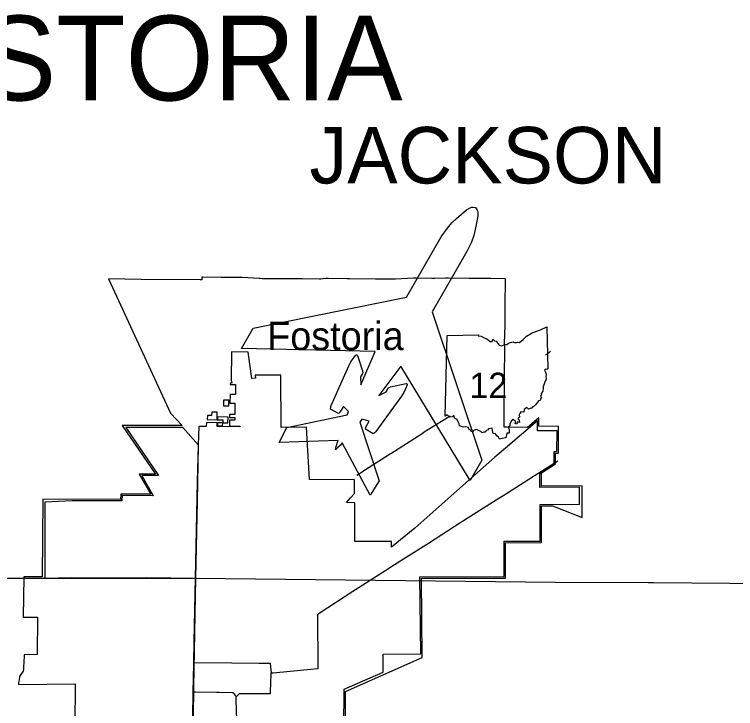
# Model space of a CAD drawing. Extents: x -232 to 448, y 619 to 1059.
# Drawn here: x 199.19 to 225.38, y 743.64 to 768.85 of the extents above; entities that cross this region are included whole.
import ezdxf

# ---------------------------------------------------------------- set-up
doc = ezdxf.new("R2010")
doc.units = 0
doc.layers.add('Default', color=7, linetype='Continuous')

msp = doc.modelspace()

# ---------------------------------------------------------------- linework, layer by layer
at = {"layer": 'Default'}
for p, q in [((202.606, 759.245), (204.864, 754.373)), ((205.999, 759.307), (205.997, 759.207)), ((214.831, 754.265), (214.913, 757.194)), ((214.831, 754.265), (214.913, 757.194)), ((207.071, 756.596), (207.064, 755.569)), ((207.681, 756.592), (207.071, 756.596)), ((207.82, 755.626), (207.681, 756.592)), ((208.868, 755.751), (207.93, 755.746)), ((207.93, 755.746), (207.944, 755.644)), ((208.879, 753.854), (208.868, 755.751)), ((207.035, 755.467), (207.034, 755.416)), ((207.086, 755.466), (207.035, 755.467)), ((207.064, 755.569), (207.086, 755.466)), ((207.944, 755.644), (207.82, 755.626)), ((207.034, 755.416), (207.224, 755.412)), ((207.224, 755.412), (207.216, 755.044)), ((207.026, 755.048), (207.02, 754.736)), ((207.216, 755.044), (207.026, 755.048)), ((206.975, 754.839), (206.785, 754.839)), ((206.785, 754.839), (206.785, 754.632)), ((206.975, 754.632), (206.975, 754.839)), ((207.02, 754.736), (207.192, 754.736)), ((207.192, 754.736), (207.192, 754.321)), ((206.357, 754.408), (206.355, 754.284)), ((206.557, 754.404), (206.357, 754.408)), ((206.556, 754.133), (206.557, 754.404)), ((206.785, 754.632), (206.975, 754.632)), ((206.2, 754.287), (206.198, 754.14)), ((206.355, 754.284), (206.2, 754.287)), ((206.571, 754.237), (206.569, 754.133)), ((206.95, 754.228), (206.571, 754.237)), ((206.946, 754.017), (206.95, 754.228)), ((207.192, 754.321), (207.006, 754.321)), ((207.006, 754.321), (207.006, 754.218)), ((207.006, 754.218), (207.192, 754.218)), ((207.192, 754.218), (207.192, 754.114)), ((218.235, 753.895), (218.238, 754.2)), ((206.164, 754.033), (206.161, 753.888)), ((206.555, 754.025), (206.164, 754.033)), ((206.198, 754.14), (206.556, 754.133)), ((206.555, 753.887), (206.555, 754.025)), ((206.566, 754.025), (206.564, 753.917)), ((206.564, 753.917), (206.754, 753.912)), ((206.756, 754.021), (206.566, 754.025)), ((206.569, 754.133), (206.758, 754.129)), ((206.754, 753.912), (206.756, 754.021)), ((206.758, 754.129), (206.756, 754.021)), ((206.756, 754.021), (206.946, 754.017)), ((207.192, 754.114), (207.006, 754.114)), ((207.006, 754.114), (207.006, 753.907)), ((207.006, 753.907), (207.384, 753.899)), ((207.384, 753.899), (207.384, 753.873)), ((218.182, 753.735), (218.186, 754.088)), ((218.953, 753.888), (218.235, 753.895)), ((209.799, 753.86), (208.879, 753.854)), ((209.905, 751.961), (209.799, 753.86)), ((218.901, 753.728), (218.182, 753.735)), ((218.894, 752.975), (218.901, 753.728)), ((218.787, 752.532), (218.791, 752.976)), ((218.791, 752.976), (218.894, 752.975)), ((218.276, 752.186), (218.787, 752.532)), ((204.312, 752.154), (203.727, 752.157)), ((203.727, 752.157), (204.149, 751.426)), ((204.43, 752.102), (203.816, 752.105)), ((203.816, 752.105), (204.238, 751.374)), ((218.278, 751.672), (218.276, 752.186)), ((211.537, 751.948), (209.905, 751.961)), ((211.543, 751.459), (211.537, 751.948)), ((219.712, 751.679), (218.278, 751.672)), ((219.709, 751.062), (219.712, 751.679)), ((203.061, 751.436), (203.048, 751.235)), ((203.109, 751.384), (203.096, 751.183)), ((200.231, 751.25), (200.199, 748.427)), ((203.048, 751.235), (200.231, 751.25)), ((201.305, 751.193), (201.289, 751.193)), ((203.096, 751.183), (201.305, 751.193)), ((218.279, 751.057), (219.709, 751.062)), ((218.282, 749.723), (218.279, 751.057)), ((218.731, 751.007), (219.809, 750.578)), ((212.886, 749.708), (211.552, 749.714)), ((212.885, 749.503), (212.886, 749.708)), ((216.976, 749.72), (218.282, 749.723)), ((216.979, 748.437), (216.976, 749.72)), ((199.532, 748.428), (199.515, 746.966)), ((200.199, 748.427), (199.532, 748.428)), ((213.918, 748.43), (216.979, 748.437)), ((213.946, 745.632), (213.918, 748.43)), ((213.97, 748.379), (217.03, 748.386)), ((213.999, 745.494), (213.97, 748.379)), ((199.515, 746.966), (200.028, 746.964)), ((200.028, 746.964), (200.026, 745.614)), ((199.545, 745.599), (199.537, 745.303)), ((200.026, 745.614), (199.545, 745.599)), ((201.401, 744.541), (201.381, 741.955))]:
    msp.add_line(p, q, dxfattribs=at)
for points in [[(212.292, 756.611), (207.442, 756.721), (207.865, 757.454), (213.433, 758.587), (214.695, 760.773), (214.914, 761.085), (215.077, 761.277), (215.245, 761.438), (215.613, 761.753), (215.741, 761.83), (215.794, 761.847), (215.842, 761.855), (215.934, 761.843)], [(215.934, 761.843), (215.989, 761.77), (216.006, 761.724), (216.019, 761.67), (216.016, 761.52), (215.927, 761.044), (215.872, 760.818), (215.787, 760.582), (215.626, 760.236), (214.364, 758.049), (216.167, 752.661), (215.744, 751.928), (213.223, 756.074)], [(205.997, 759.207), (205.943, 759.208), (203.796, 759.231), (202.606, 759.245)], [(207.408, 759.295), (206.734, 759.295), (206.697, 759.296), (206.04, 759.307), (205.999, 759.307)], [(210.324, 759.237), (210.271, 759.238), (209.647, 759.251), (209.595, 759.252), (209.544, 759.252), (209.076, 759.247), (208.985, 759.246), (208.971, 759.246), (208.19, 759.255), (208.116, 759.256), (208.084, 759.258), (207.46, 759.292), (207.408, 759.295)], [(212.975, 759.241), (212.919, 759.241), (212.422, 759.243), (212.332, 759.243), (212.311, 759.243), (211.372, 759.247), (211.311, 759.247), (211.261, 759.248), (210.598, 759.259), (210.496, 759.261), (210.387, 759.245), (210.324, 759.237)], [(214.899, 759.271), (214.844, 759.27), (214.459, 759.267), (214.362, 759.267), (214.348, 759.267), (213.799, 759.27), (213.732, 759.271), (213.691, 759.269), (213.032, 759.243), (212.975, 759.241)], [(217.021, 759.248), (216.488, 759.264), (216.412, 759.267), (216.384, 759.267), (215.801, 759.265), (215.727, 759.264), (215.694, 759.265), (214.951, 759.27), (214.899, 759.271)], [(217.011, 758.2), (217.011, 758.258), (217.021, 759.248)], [(216.992, 755.151), (216.987, 755.795), (216.986, 755.811), (216.988, 755.901), (217.001, 756.528), (217.001, 756.534), (216.999, 756.631), (216.995, 756.997), (216.994, 757.025), (216.996, 757.103), (217.008, 757.678), (217.009, 757.701), (217.009, 757.781), (217.011, 758.147), (217.011, 758.2)], [(214.913, 757.194), (216.05, 757.213), (216.032, 757.178), (216.139, 757.171), (216.253, 757.108), (216.349, 757.068), (216.467, 756.975), (216.538, 756.976), (216.568, 757.053), (216.622, 756.994), (216.686, 756.983), (216.796, 756.843), (216.888, 756.813), (216.997, 756.861), (217.079, 756.869), (217.139, 756.916), (217.295, 756.957), (217.339, 756.932), (217.421, 756.937), (217.463, 756.955), (217.535, 756.939), (217.662, 757.046), (217.792, 757.171), (217.993, 757.29), (218.292, 757.402), (218.53, 757.502), (218.564, 755.982)], [(214.913, 757.194), (216.05, 757.213), (216.032, 757.178), (216.139, 757.171), (216.253, 757.108), (216.349, 757.068), (216.467, 756.975), (216.538, 756.976), (216.568, 757.053), (216.622, 756.994), (216.686, 756.983), (216.796, 756.843), (216.888, 756.813), (216.997, 756.861), (217.079, 756.869), (217.139, 756.916), (217.295, 756.957), (217.339, 756.932), (217.421, 756.937), (217.463, 756.955), (217.535, 756.939), (217.662, 757.046), (217.792, 757.171), (217.993, 757.29), (218.292, 757.402), (218.53, 757.502), (218.564, 755.982)], [(210.854, 753.044), (210.875, 753.159), (210.909, 753.281), (210.946, 753.373), (208.802, 753.306), (209.087, 753.851), (211.275, 754.312), (211.329, 754.43), (211.138, 754.616), (211.039, 754.446), (211.002, 754.397), (210.98, 754.376), (210.957, 754.356), (210.672, 754.52), (210.675, 754.558), (210.68, 754.588), (210.687, 754.618), (210.697, 754.647), (211.339, 756.095), (211.414, 756.23), (211.5, 756.357), (211.596, 756.477), (211.612, 756.486), (211.627, 756.487), (211.64, 756.479), (211.649, 756.464), (211.833, 755.911), (211.838, 755.885), (211.842, 755.856), (211.842, 755.84), (211.834, 755.817), (211.76, 755.69), (211.776, 755.395), (212.292, 756.611)], [(218.473, 756.493), (218.552, 756.543), (218.618, 756.586), (218.665, 756.621)], [(213.223, 756.074), (212.428, 755.018), (212.691, 755.152), (212.764, 755.279), (212.781, 755.298), (212.795, 755.306), (212.822, 755.317), (212.846, 755.326), (213.418, 755.443), (213.435, 755.443), (213.448, 755.435), (213.455, 755.422), (213.455, 755.404), (213.4, 755.26), (213.333, 755.122), (213.253, 754.99), (212.32, 753.71), (212.3, 753.687), (212.278, 753.666), (212.254, 753.646), (212.222, 753.625), (211.938, 753.789), (211.943, 753.82), (211.951, 753.849), (211.975, 753.906), (212.073, 754.076), (211.815, 754.149), (211.741, 754.043), (212.436, 751.917), (212.106, 751.398), (211.092, 753.289), (211.031, 753.211), (210.942, 753.121), (210.854, 753.044)], [(218.564, 755.982), (218.529, 755.961), (218.474, 755.971), (218.438, 755.929), (218.483, 755.857), (218.504, 755.782), (218.485, 755.699), (218.504, 755.631), (218.491, 755.574), (218.457, 755.517), (218.445, 755.463), (218.416, 755.406), (218.419, 755.374), (218.391, 755.348), (218.396, 755.253), (218.382, 755.201), (218.387, 755.155), (218.342, 755.143), (218.352, 755.106), (218.323, 755.077), (218.33, 755.027), (218.297, 754.995), (218.329, 754.931), (218.303, 754.911), (218.282, 754.833), (218.225, 754.818), (218.109, 754.676), (218.068, 754.622), (218.022, 754.609), (217.997, 754.554), (217.941, 754.554), (217.855, 754.515), (217.8, 754.581), (217.704, 754.502), (217.692, 754.411), (217.57, 754.414), (217.575, 754.367), (217.548, 754.354), (217.523, 754.308), (217.537, 754.226), (217.48, 754.205), (217.487, 754.157), (217.524, 754.128), (217.54, 754.036), (217.479, 754.055), (217.429, 753.978), (217.378, 753.996), (217.395, 754.061), (217.308, 754.14), (217.226, 754.077), (217.184, 753.977), (217.183, 753.909), (217.122, 753.868), (217.161, 753.773), (217.154, 753.708), (217.155, 753.645), (217.079, 753.648), (217.033, 753.479)], [(218.564, 755.982), (218.529, 755.961), (218.474, 755.971), (218.438, 755.929), (218.483, 755.857), (218.504, 755.782), (218.485, 755.699), (218.504, 755.631), (218.491, 755.574), (218.457, 755.517), (218.445, 755.463), (218.416, 755.406), (218.419, 755.374), (218.391, 755.348), (218.396, 755.253), (218.382, 755.201), (218.387, 755.155), (218.342, 755.143), (218.352, 755.106), (218.323, 755.077), (218.33, 755.027), (218.297, 754.995), (218.329, 754.931), (218.303, 754.911), (218.282, 754.833), (218.225, 754.818), (218.109, 754.676), (218.068, 754.622), (218.022, 754.609), (217.997, 754.554), (217.941, 754.554), (217.855, 754.515), (217.8, 754.581), (217.704, 754.502), (217.692, 754.411), (217.57, 754.414), (217.575, 754.367), (217.548, 754.354), (217.523, 754.308), (217.537, 754.226), (217.48, 754.205), (217.487, 754.157), (217.524, 754.128), (217.54, 754.036), (217.479, 754.055), (217.429, 753.978), (217.378, 753.996), (217.395, 754.061), (217.308, 754.14), (217.226, 754.077), (217.184, 753.977), (217.183, 753.909), (217.122, 753.868), (217.161, 753.773), (217.154, 753.708), (217.155, 753.645), (217.079, 753.648), (217.033, 753.479)], [(216.977, 754.78), (216.979, 754.844), (216.992, 755.151)], [(216.972, 753.866), (216.972, 753.91), (216.976, 754.722), (216.977, 754.78)], [(204.864, 754.373), (205.28, 753.919)], [(211.625, 752.125), (211.854, 752.269), (211.882, 752.287), (211.945, 752.327), (212.812, 752.879), (212.858, 752.908), (213.999, 753.638), (214.077, 753.688), (215.013, 754.28)], [(217.033, 753.479), (216.9, 753.447), (216.808, 753.428), (216.776, 753.504), (216.71, 753.545), (216.667, 753.622), (216.572, 753.632), (216.55, 753.738), (216.539, 753.823), (216.41, 753.802), (216.375, 753.75), (216.329, 753.736), (216.302, 753.683), (216.24, 753.678), (216.173, 753.654), (216.129, 753.705), (216.019, 753.757), (215.97, 753.784), (215.866, 753.743), (215.844, 753.693), (215.762, 753.715), (215.743, 753.77), (215.693, 753.786), (215.682, 753.845), (215.576, 753.876), (215.494, 753.864), (215.351, 753.91), (215.342, 753.987), (215.293, 754.081), (215.268, 754.146), (215.177, 754.195), (215.159, 754.272), (215.13, 754.27), (215.103, 754.239), (215.003, 754.224), (214.962, 754.256), (214.906, 754.31), (214.831, 754.265)], [(217.033, 753.479), (216.9, 753.447), (216.808, 753.428), (216.776, 753.504), (216.71, 753.545), (216.667, 753.622), (216.572, 753.632), (216.55, 753.738), (216.539, 753.823), (216.41, 753.802), (216.375, 753.75), (216.329, 753.736), (216.302, 753.683), (216.24, 753.678), (216.173, 753.654), (216.129, 753.705), (216.019, 753.757), (215.97, 753.784), (215.866, 753.743), (215.844, 753.693), (215.762, 753.715), (215.743, 753.77), (215.693, 753.786), (215.682, 753.845), (215.576, 753.876), (215.494, 753.864), (215.351, 753.91), (215.342, 753.987), (215.293, 754.081), (215.268, 754.146), (215.177, 754.195), (215.159, 754.272), (215.13, 754.27), (215.103, 754.239), (215.003, 754.224), (214.962, 754.256), (214.906, 754.31), (214.831, 754.265)], [(218.238, 754.2), (217.829, 753.85)], [(205.28, 753.919), (203.108, 753.919)], [(203.108, 753.919), (204.312, 752.154)], [(206.161, 753.888), (205.885, 753.893), (205.871, 753.206)], [(207.384, 753.873), (206.555, 753.887)], [(218.186, 754.088), (217.031, 753.102), (216.643, 752.768), (215.257, 751.547), (213.738, 750.201), (212.885, 749.503)], [(218.838, 752.526), (218.842, 752.924), (218.945, 752.923), (218.953, 753.888)], [(205.874, 753.215), (205.304, 753.848), (203.234, 753.856)], [(203.234, 753.856), (204.43, 752.102)], [(217.829, 753.85), (217.078, 753.864), (216.972, 753.866)], [(205.871, 753.206), (205.83, 751.168), (205.796, 749.489), (205.775, 748.382)], [(205.81, 750.105), (205.846, 751.892), (205.874, 753.215)], [(218.331, 752.267), (218.926, 752.642)], [(218.328, 752.204), (218.838, 752.526)], [(216.962, 751.396), (218.011, 752.065), (218.018, 752.07), (218.102, 752.122), (218.331, 752.267)], [(219.809, 750.578), (219.815, 751.731), (218.329, 751.724), (218.328, 752.204)], [(204.149, 751.426), (203.061, 751.436)], [(204.238, 751.374), (203.109, 751.384)], [(211.251, 751.127), (211.394, 751.293), (211.543, 751.459)], [(211.715, 748.052), (212.808, 748.752), (212.811, 748.754), (212.9, 748.81), (214.133, 749.593), (214.153, 749.606), (214.224, 749.651), (215.408, 750.411), (215.423, 750.42), (215.499, 750.469), (216.688, 751.221), (216.722, 751.243), (216.779, 751.279), (216.962, 751.396)], [(201.289, 751.193), (200.298, 751.144), (200.298, 748.382), (201.257, 748.399)], [(211.552, 749.714), (211.557, 751.112), (211.251, 751.127)], [(217.03, 748.386), (217.027, 749.669), (218.334, 749.672), (218.331, 751.006), (218.731, 751.007)], [(205.775, 748.382), (205.81, 750.105)], [(173.472, 748.559), (174.333, 748.549), (176.635, 748.51), (178.125, 748.473), (180.056, 748.405), (181.299, 748.442), (182.608, 748.401), (183.488, 748.382), (184.459, 748.339), (192.227, 748.384), (205.775, 748.382)], [(201.257, 748.399), (203.052, 748.398), (203.975, 748.405)], [(203.975, 748.405), (205.775, 748.382)], [(205.466, 715.722), (205.495, 728.959), (205.546, 732.775), (205.66, 739.616), (205.674, 743.483), (205.775, 748.382)], [(205.775, 748.382), (205.693, 744.415)], [(205.727, 746.071), (205.775, 748.382)], [(205.775, 748.382), (218.839, 748.24), (222.221, 748.221), (222.402, 748.227), (227.948, 748.176), (233.391, 748.153), (238.85, 748.082)], [(210.221, 747.078), (210.264, 747.107), (211.487, 747.906), (211.488, 747.907), (211.578, 747.965), (211.715, 748.052)], [(210.204, 745.094), (210.218, 745.095), (210.218, 745.19), (210.208, 747.029), (210.208, 747.07), (210.221, 747.078)], [(205.712, 745.314), (205.727, 746.071)], [(211.975, 742.932), (211.964, 743.245), (211.851, 743.248), (211.836, 742.935), (211.16, 742.934), (211.166, 744.351), (212.585, 744.967), (212.586, 745.62), (213.946, 745.632)], [(199.537, 745.303), (199.523, 745.183), (199.525, 745.085), (199.511, 745.007), (199.449, 744.914), (199.379, 744.81), (199.361, 744.694), (199.346, 744.588), (199.343, 744.517)], [(207.249, 744.071), (207.221, 744.117), (207.189, 744.17), (207.128, 744.221), (206.64, 744.23), (206.534, 744.231), (205.775, 744.243), (205.69, 744.244), (205.71, 745.219), (205.71, 745.219), (205.712, 745.314)], [(205.712, 745.314), (207.084, 745.303)], [(207.084, 745.303), (208.072, 745.295)], [(208.072, 745.295), (208.484, 745.292), (208.486, 745.265)], [(208.486, 745.265), (208.517, 744.939)], [(211.217, 744.26), (213.999, 745.494)], [(208.515, 744.903), (208.517, 744.939), (208.588, 744.946), (210.204, 745.094)], [(207.738, 744.196), (208.492, 744.196), (208.494, 744.254), (208.515, 744.903)], [(199.343, 744.517), (201.401, 744.541)], [(205.693, 744.415), (205.67, 742.281), (205.66, 739.616)], [(207.249, 744.071), (207.287, 744.109), (207.364, 744.186), (207.374, 744.196), (207.412, 744.196)], [(207.412, 744.196), (207.738, 744.196)], [(212.024, 742.982), (212.014, 743.295), (211.802, 743.301), (211.787, 742.986), (211.211, 742.985), (211.217, 744.26)], [(207.239, 742.288), (207.264, 743.154), (207.265, 743.22), (207.251, 743.978), (207.249, 744.071)]]:
    msp.add_lwpolyline(points, dxfattribs=at)

# ---------------------------------------------------------------- texts
for s, height, p in [('FOSTORIA', 3.078, (192.252, 765.727)), ('JACKSON', 2.052, (209.906, 762.713)), ('Fostoria                   ', 1.026, (208.372, 756.662)), ('12', 0.9234, (215.717, 754.918))]:
    msp.add_text(s, height=height, dxfattribs=at).set_placement(p)

doc.saveas('drawing.dxf')
